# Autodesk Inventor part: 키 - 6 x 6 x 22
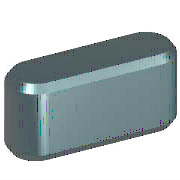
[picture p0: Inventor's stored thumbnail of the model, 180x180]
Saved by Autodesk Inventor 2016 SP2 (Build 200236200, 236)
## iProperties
IsCustomPart: 1
Created: 2012-02
Part Number: 키 - 6 x 6 x 22
Material: 강철, 연강
Description: 키 및 해당 키홈
Document SubType Name: Modeling
Standard: KS B 1311
Designer: mduedu
Standards Organization: KS
Language: ko-KR
Size Designation: 6 x 6 x 22
Categories: <MemberInstance><Categories><Category DisplayName="샤프트 부품" InternalName="7f7aeb1f-a693-4053-b835-cee3144e0d98" Mnemonic="SHFT"><Category DisplayName="키" Interna
Density: 7.86 g/cm^3
Mass: 5.79788 g
Surface Area: 5.294 cm^2
Volume: 0.737644 cm^3
Appearance: 노란색
Author: mduedu
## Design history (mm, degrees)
workplane "Work Plane1"
workplane "Work Plane2"
sketch "스케치1"
  geometry: L1 (3, 3)-(19, 3); L2 (19, -3)-(3, -3); L3 (0, 9.4)-(0, -7.4) reference; L4 (-5, 0)-(30, 0) reference; L5 (22, 0)-(22, 7); A1 r 3 centre (3, 0) between (3, 3) and (3, -3); A2 r 3 centre (19, 0) between (19, -3) and (19, 3)
  constraints: 6 end point, 5 point on circle, 4 tangent, 3 point on line, 2 centre point, 1 horizontal, 1 parallel, 1 perpendicular
  dimensions: "d0" = 3 radius of A1 (= 0.5 x PB); "d13" = 3 radius of A2 (= 0.5 x PB); "d14" = 22 distance between parallel lines of L5 L3 (= NLG)
extrude "본체1" new body sketch "스케치1" taper "d3" = 0 deg; stored distance "d4" = 10
workplane "Work Plane3"
body "Solid1"
chamfer "모따기1" distance "d8" = 0.4 (= PHH); stored, may be unused: second distance "d9" = 0.4 (= PHH), angle "d15" = 45 deg
other parameters: "d1" = -3.5 (= -PNT), "d2" = 2.5 (= PH - PNT), "NLG" = 22 [user parameter; used in 3 equation terms], "PB" = 6 [user parameter; used in 2 equation terms], "PNT" = 3.5 [user parameter; used in 2 equation terms], "PH" = 6 [user parameter; used in 1 equation term], "PHH" = 0.4 [user parameter; used in 2 equation terms], "d10" = 0, "d16" = 0, "d17" = 0, "d18" = 0, "WDMIN" = 17 [user parameter], "PLB2" = 22 (= NLG) [user parameter], "WDMAX" = 22 [user parameter], "PLB1" = 22 (= NLG) [user parameter], "RR" = 0.16 [user parameter], "PUEB" = 2.8 [user parameter]
